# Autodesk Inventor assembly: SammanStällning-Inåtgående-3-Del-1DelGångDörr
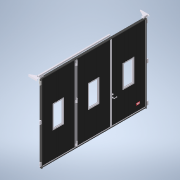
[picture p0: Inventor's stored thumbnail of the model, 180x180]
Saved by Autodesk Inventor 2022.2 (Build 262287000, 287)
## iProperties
Created: 2022-02
Part Number: SammanStällning-Inåtgående-3-Del-1DelGångDörr
Document SubType Name: Assembly
Designer: cl
Author: cl
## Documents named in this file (20)
- G:\AutoCad\Carl Lund\3D-modeller systemlösningar\3D-modell-systemlösning-2022\SammanStällning-Inåtgående-3-Del-1DelGångDörr.iam
- G:\AutoCad\Carl Lund\3D-modeller systemlösningar\3D-modell-systemlösning-2022\Parts\BladKomplett2022.iam
- G:\AutoCad\Carl Lund\3D-modeller systemlösningar\3D-modell-systemlösning-2022\Parts\MellanGångjärnH.ipt
- G:\AutoCad\Carl Lund\3D-modeller systemlösningar\3D-modell-systemlösning-2022\Parts\MellanGångjärnV.ipt
- G:\AutoCad\Carl Lund\3D-modeller systemlösningar\3D-modell-systemlösning-2022\Parts\Karmstyrning.ipt
- G:\AutoCad\Carl Lund\3D-modeller systemlösningar\3D-modell-systemlösning-2022\Parts\KarmgångjärnH.ipt
- G:\AutoCad\Carl Lund\3D-modeller systemlösningar\3D-modell-systemlösning-2022\Parts\KarmgångjärnV.ipt
- G:\AutoCad\Carl Lund\3D-modeller systemlösningar\3D-modell-systemlösning-2022\Parts\SidotätningUppe.ipt
- G:\AutoCad\Carl Lund\3D-modeller systemlösningar\3D-modell-systemlösning-2022\Parts\SidoTätning.ipt
- G:\AutoCad\Carl Lund\3D-modeller systemlösningar\3D-modell-systemlösning-2022\Parts\SläpList.ipt
- G:\AutoCad\Carl Lund\3D-modeller systemlösningar\3D-modell-systemlösning-2022\Parts\GummilistMellan.ipt
- G:\AutoCad\Carl Lund\3D-modeller systemlösningar\3D-modell-systemlösning-2022\Styrande.iam
- G:\AutoCad\Carl Lund\3D-modeller systemlösningar\3D-modell-systemlösning-2022\Parts\GarageregelHöger.ipt
- G:\AutoCad\Carl Lund\3D-modeller systemlösningar\3D-modell-systemlösning-2022\Parts\UppställningsbeslagHöger.ipt
- G:\AutoCad\Carl Lund\3D-modeller systemlösningar\3D-modell-systemlösning-2022\Parts\UppställningsbeslagVänster.ipt
- G:\AutoCad\Carl Lund\3D-modeller systemlösningar\3D-modell-systemlösning-2022\Parts\styrrulle.ipt
- G:\AutoCad\Carl Lund\3D-modeller systemlösningar\3D-modell-systemlösning-2022\Parts\Styrskena.ipt
- G:\AutoCad\Carl Lund\3D-modeller systemlösningar\3D-modell-systemlösning-2022\Parts\Anslagslist.ipt
- G:\AutoCad\Carl Lund\3D-modeller systemlösningar\3D-modell-systemlösning-2022\Parts\DörrHandtag-H.ipt
- G:\AutoCad\Carl Lund\3D-modeller systemlösningar\3D-modell-systemlösning-2022\Parts\Logga.ipt
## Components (41 placed, 18 different names)
1. DörrHandtag-H:1 — Mate:183, Mate:184, Mate:185, Mate:186
2. Logga:1 — Mate:187, Mate:188, Mate:189
3. BladKomplett2022:1 [sub-assembly] — Mate:1, Mate:2, Flush:1, Flush:2, Flush:3, Flush:8, Flush:28, Flush:29, Mate:28, Flush:30, Mate:42, Flush:73, Mate:39, Mate:43, Mate:47, Mate:48, Flush:99, Flush:100, Flush:101, Flush:102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
4. BladKomplett2022:2 [sub-assembly] — Flush:2, Flush:3, Flush:8, Flush:106, Mate:52, Flush:107, Flush:118, Flush:121, Mate:82, Flush:170, Flush:171, Mate:180, Mate:182, Flush:178
5. BladKomplett2022:3 [sub-assembly] — Flush:30, Flush:101, Flush:102, Mate:53, Flush:114, Flush:115
6. BladKomplett2022:4 [sub-assembly] — Flush:32, Flush:100, Flush:103, Mate:54, Flush:122, Flush:123, Flush:128, Mate:178
7. BladKomplett2022:5 [sub-assembly] — Flush:31, Flush:99, Flush:104, Flush:129, Mate:55, Flush:130, Mate:81, Flush:168, Flush:169, Mate:184
8. BladKomplett2022:6 [sub-assembly] — Mate:28, Flush:28, Flush:29, Flush:31, Flush:32, Mate:38, Flush:74, Mate:49, Mate:50, Flush:131, Flush:134, Flush:137, Mate:56, Flush:138, Flush:139, Mate:58, Mate:59, Flush:152, Mate:69, Mate:70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
9. GarageregelHöger:1 — Flush:156, Flush:157, Flush:158
10. GarageregelHöger:2 — Mate:77, Flush:154, Flush:155, Flush:156, Flush:157, Flush:158
11. Karmstyrning:2 — Mate:38, Mate:56, Flush:138, Flush:141
12. Karmstyrning:3 — Mate:39, Mate:43, Flush:140
13. Karmstyrning:4 — Mate:42, Mate:60, Mate:61, Flush:141
14. KarmgångjärnH:1 — Flush:74, Mate:49, Mate:50, Flush:166, Flush:167, Mate:80
15. KarmgångjärnV:1 — Flush:73, Mate:47, Mate:48, Flush:164, Flush:165, Mate:79
16. Karmstyrning:1 — Flush:139, Mate:58, Mate:59, Flush:140
17. MellanGångjärnV:3 — Flush:110, Flush:111, Flush:113
18. MellanGångjärnV:2 — Flush:108, Flush:109, Flush:110, Flush:111, Flush:112
19. MellanGångjärnV:1 — Flush:106, Mate:52, Flush:107, Flush:108, Flush:109
20. MellanGångjärnH:2 — Flush:116, Flush:117, Flush:118, Flush:119, Flush:120
21. MellanGångjärnH:3 — Flush:119, Flush:120, Flush:121
22. MellanGångjärnH:1 — Mate:53, Flush:114, Flush:115, Flush:116, Flush:117
23. MellanGångjärnV:6 — Flush:124, Flush:125, Flush:126, Flush:127, Flush:128
24. MellanGångjärnV:5 — Flush:126, Flush:127, Flush:129
25. MellanGångjärnV:4 — Mate:54, Flush:122, Flush:123, Flush:124, Flush:125
26. MellanGångjärnH:5 — Flush:132, Flush:133, Flush:134
27. MellanGångjärnH:6 — Flush:135, Flush:136, Flush:137
28. MellanGångjärnH:4 — Mate:55, Flush:130, Flush:131, Flush:132, Flush:133, Flush:135, Flush:136
29. GummilistMellan:5 — Mate:66, Flush:150, Flush:151
30. SidotätningUppe:1 — Mate:67, Mate:68, Flush:152, Mate:71, Mate:74
31. SidoTätning:1 — Mate:69, Mate:70, Mate:71, Mate:76
32. SidoTätning:2 — Mate:72, Mate:73, Mate:74
33. SläpList:1 — Mate:75, Flush:153, Mate:76, Mate:183
34. UppställningsbeslagVänster:1 — Flush:166, Flush:167, Mate:80
35. styrrulle:1 — Mate:81, Flush:168, Flush:169
36. styrrulle:2 — Mate:82, Flush:170, Flush:171, Tangent:1
37. Styrskena:1 — Mate:83, Flush:172, Tangent:1, Flush:174, Mate:176, Flush:175
38. Styrskena:2 — Flush:174, Mate:176, Flush:175
39. UppställningsbeslagHöger:1 — Flush:164, Flush:165, Mate:79, Mate:83, Flush:172
40. Anslagslist:1 — Mate:178, Mate:182, Flush:178
41. Anslagslist:2 — Mate:180, Mate:181, Flush:177
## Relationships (125: Flush 75, Mate 49, Tangent 1)
- Mate:1: BladKomplett2022:1
- Mate:2: BladKomplett2022:1
- Flush:1: BladKomplett2022:1
- Flush:2: BladKomplett2022:1 ↔ BladKomplett2022:2
- Flush:3: BladKomplett2022:1 ↔ BladKomplett2022:2
- Flush:8: BladKomplett2022:1 ↔ BladKomplett2022:2
- Mate:28: BladKomplett2022:1 ↔ BladKomplett2022:6
- Flush:28: BladKomplett2022:1 ↔ BladKomplett2022:6
- Flush:29: BladKomplett2022:1 ↔ BladKomplett2022:6
- Flush:30: BladKomplett2022:1 ↔ BladKomplett2022:3
- Flush:31: BladKomplett2022:5 ↔ BladKomplett2022:6
- Flush:32: BladKomplett2022:4 ↔ BladKomplett2022:6
- Mate:38: BladKomplett2022:6 ↔ Karmstyrning:2
- Mate:39: BladKomplett2022:1 ↔ Karmstyrning:3
- Mate:42: BladKomplett2022:1 ↔ Karmstyrning:4
- Mate:43: BladKomplett2022:1 ↔ Karmstyrning:3
- Flush:73: BladKomplett2022:1 ↔ KarmgångjärnV:1
- Mate:47: BladKomplett2022:1 ↔ KarmgångjärnV:1
- Mate:48: BladKomplett2022:1 ↔ KarmgångjärnV:1
- Flush:74: BladKomplett2022:6 ↔ KarmgångjärnH:1
- Mate:49: BladKomplett2022:6 ↔ KarmgångjärnH:1
- Mate:50: BladKomplett2022:6 ↔ KarmgångjärnH:1
- Flush:99: BladKomplett2022:1 ↔ BladKomplett2022:5
- Flush:100: BladKomplett2022:1 ↔ BladKomplett2022:4
- Flush:101: BladKomplett2022:1 ↔ BladKomplett2022:3
- Flush:102: BladKomplett2022:1 ↔ BladKomplett2022:3
- Flush:103: BladKomplett2022:1 ↔ BladKomplett2022:4
- Flush:104: BladKomplett2022:1 ↔ BladKomplett2022:5
- Flush:106: BladKomplett2022:2 ↔ MellanGångjärnV:1
- Mate:52: BladKomplett2022:2 ↔ MellanGångjärnV:1
- Flush:107: BladKomplett2022:2 ↔ MellanGångjärnV:1
- Flush:108: MellanGångjärnV:2 ↔ MellanGångjärnV:1
- Flush:109: MellanGångjärnV:2 ↔ MellanGångjärnV:1
- Flush:110: MellanGångjärnV:3 ↔ MellanGångjärnV:2
- Flush:111: MellanGångjärnV:3 ↔ MellanGångjärnV:2
- Flush:112: BladKomplett2022:1 ↔ MellanGångjärnV:2
- Flush:113: BladKomplett2022:1 ↔ MellanGångjärnV:3
- Mate:53: BladKomplett2022:3 ↔ MellanGångjärnH:1
- Flush:114: BladKomplett2022:3 ↔ MellanGångjärnH:1
- Flush:115: BladKomplett2022:3 ↔ MellanGångjärnH:1
- Flush:116: MellanGångjärnH:2 ↔ MellanGångjärnH:1
- Flush:117: MellanGångjärnH:2 ↔ MellanGångjärnH:1
- Flush:118: BladKomplett2022:2 ↔ MellanGångjärnH:2
- Flush:119: MellanGångjärnH:2 ↔ MellanGångjärnH:3
- Flush:120: MellanGångjärnH:2 ↔ MellanGångjärnH:3
- Flush:121: BladKomplett2022:2 ↔ MellanGångjärnH:3
- Mate:54: BladKomplett2022:4 ↔ MellanGångjärnV:4
- Flush:122: BladKomplett2022:4 ↔ MellanGångjärnV:4
- Flush:123: BladKomplett2022:4 ↔ MellanGångjärnV:4
- Flush:124: MellanGångjärnV:6 ↔ MellanGångjärnV:4
- Flush:125: MellanGångjärnV:6 ↔ MellanGångjärnV:4
- Flush:126: MellanGångjärnV:6 ↔ MellanGångjärnV:5
- Flush:127: MellanGångjärnV:6 ↔ MellanGångjärnV:5
- Flush:128: BladKomplett2022:4 ↔ MellanGångjärnV:6
- Flush:129: BladKomplett2022:5 ↔ MellanGångjärnV:5
- Mate:55: BladKomplett2022:5 ↔ MellanGångjärnH:4
- Flush:130: BladKomplett2022:5 ↔ MellanGångjärnH:4
- Flush:131: BladKomplett2022:6 ↔ MellanGångjärnH:4
- Flush:132: MellanGångjärnH:5 ↔ MellanGångjärnH:4
- Flush:133: MellanGångjärnH:5 ↔ MellanGångjärnH:4
- Flush:134: BladKomplett2022:6 ↔ MellanGångjärnH:5
- Flush:135: MellanGångjärnH:6 ↔ MellanGångjärnH:4
- Flush:136: MellanGångjärnH:6 ↔ MellanGångjärnH:4
- Flush:137: BladKomplett2022:6 ↔ MellanGångjärnH:6
- Mate:56: BladKomplett2022:6 ↔ Karmstyrning:2
- Flush:138: BladKomplett2022:6 ↔ Karmstyrning:2
- Flush:139: BladKomplett2022:6 ↔ Karmstyrning:1
- Mate:58: BladKomplett2022:6 ↔ Karmstyrning:1
- Mate:59: BladKomplett2022:6 ↔ Karmstyrning:1
- Flush:140: Karmstyrning:3 ↔ Karmstyrning:1
- Mate:60: BladKomplett2022:1 ↔ Karmstyrning:4
- Mate:61: BladKomplett2022:1 ↔ Karmstyrning:4
- Flush:141: Karmstyrning:2 ↔ Karmstyrning:4
- Mate:66: BladKomplett2022:1 ↔ GummilistMellan:5
- Flush:150: BladKomplett2022:1 ↔ GummilistMellan:5
- Flush:151: BladKomplett2022:1 ↔ GummilistMellan:5
- Mate:67: BladKomplett2022:1 ↔ SidotätningUppe:1
- Mate:68: BladKomplett2022:1 ↔ SidotätningUppe:1
- Flush:152: BladKomplett2022:6 ↔ SidotätningUppe:1
- Mate:69: BladKomplett2022:6 ↔ SidoTätning:1
- Mate:70: BladKomplett2022:6 ↔ SidoTätning:1
- Mate:71: SidotätningUppe:1 ↔ SidoTätning:1
- Mate:72: BladKomplett2022:1 ↔ SidoTätning:2
- Mate:73: BladKomplett2022:1 ↔ SidoTätning:2
- Mate:74: SidotätningUppe:1 ↔ SidoTätning:2
- Mate:75: BladKomplett2022:1 ↔ SläpList:1
- Flush:153: BladKomplett2022:1 ↔ SläpList:1
- Mate:76: SidoTätning:1 ↔ SläpList:1
- Mate:77: BladKomplett2022:1 ↔ GarageregelHöger:2
- Flush:154: BladKomplett2022:1 ↔ GarageregelHöger:2
- Flush:155: BladKomplett2022:1 ↔ GarageregelHöger:2
- Flush:156: GarageregelHöger:1 ↔ GarageregelHöger:2
- Flush:157: GarageregelHöger:1 ↔ GarageregelHöger:2
- Flush:158: GarageregelHöger:1 ↔ GarageregelHöger:2
- Flush:164: KarmgångjärnV:1 ↔ UppställningsbeslagHöger:1
- Flush:165: KarmgångjärnV:1 ↔ UppställningsbeslagHöger:1
- Mate:79: KarmgångjärnV:1 ↔ UppställningsbeslagHöger:1
- Flush:166: KarmgångjärnH:1 ↔ UppställningsbeslagVänster:1
- Flush:167: KarmgångjärnH:1 ↔ UppställningsbeslagVänster:1
- Mate:80: KarmgångjärnH:1 ↔ UppställningsbeslagVänster:1
- Mate:81: BladKomplett2022:5 ↔ styrrulle:1
- Flush:168: BladKomplett2022:5 ↔ styrrulle:1
- Flush:169: BladKomplett2022:5 ↔ styrrulle:1
- Mate:82: BladKomplett2022:2 ↔ styrrulle:2
- Flush:170: BladKomplett2022:2 ↔ styrrulle:2
- Flush:171: BladKomplett2022:2 ↔ styrrulle:2
- Mate:83: Styrskena:1 ↔ UppställningsbeslagHöger:1
- Flush:172: Styrskena:1 ↔ UppställningsbeslagHöger:1
- Tangent:1: styrrulle:2 ↔ Styrskena:1
- Flush:174: Styrskena:1 ↔ Styrskena:2
- Mate:176: Styrskena:1 ↔ Styrskena:2
- Flush:175: Styrskena:1 ↔ Styrskena:2
- Mate:178: BladKomplett2022:4 ↔ Anslagslist:1
- Mate:180: BladKomplett2022:2 ↔ Anslagslist:2
- Mate:181: BladKomplett2022:6 ↔ Anslagslist:2
- Flush:177: BladKomplett2022:6 ↔ Anslagslist:2
- Mate:182: BladKomplett2022:2 ↔ Anslagslist:1
- Flush:178: BladKomplett2022:2 ↔ Anslagslist:1
- Mate:183: DörrHandtag-H:1 ↔ SläpList:1
- Mate:184: DörrHandtag-H:1 ↔ BladKomplett2022:5
- Mate:185: DörrHandtag-H:1 ↔ BladKomplett2022:6
- Mate:186: DörrHandtag-H:1 ↔ BladKomplett2022:6
- Mate:187: Logga:1 ↔ BladKomplett2022:6
- Mate:188: Logga:1 ↔ BladKomplett2022:6
- Mate:189: Logga:1 ↔ BladKomplett2022:6
## Named parameters: Blad2 = 1363.66667 mm, Blad3 = 0, Blad4 = 0, Blad5 = 0, MGJ12Djup = 0, MGJ12Bredd = 0, MGJ56Djup = 48 mm, MGJ23Djup = 48 mm, MGJ45Djup = 48 mm, GarageRegel5 = 0, GarageRegel6 = 0, BladBredd = 1338.66667 mm, Fönsterhöjd = 862 mm, Blad2_1 = 1363.66667 mm, Blad3_1 = 0, Blad4_1 = 0, Blad5_1 = 0, Blad6 = 2025 mm, MGJ12Djup_1 = 0, MGJ12Bredd_1 = 0, MGJ2Djup = 0, MGJ2Bredd = 5012.5 mm, MGJ56Djup_1 = 48 mm, MGJ23Djup_1 = 48 mm, MGJ45Djup_1 = 48 mm, GarageRegel5_1 = 0, GarageRegel6_1 = 0, StyrskenaV = 2777.33333 mm, Styrrulle2Djup = 48 mm
